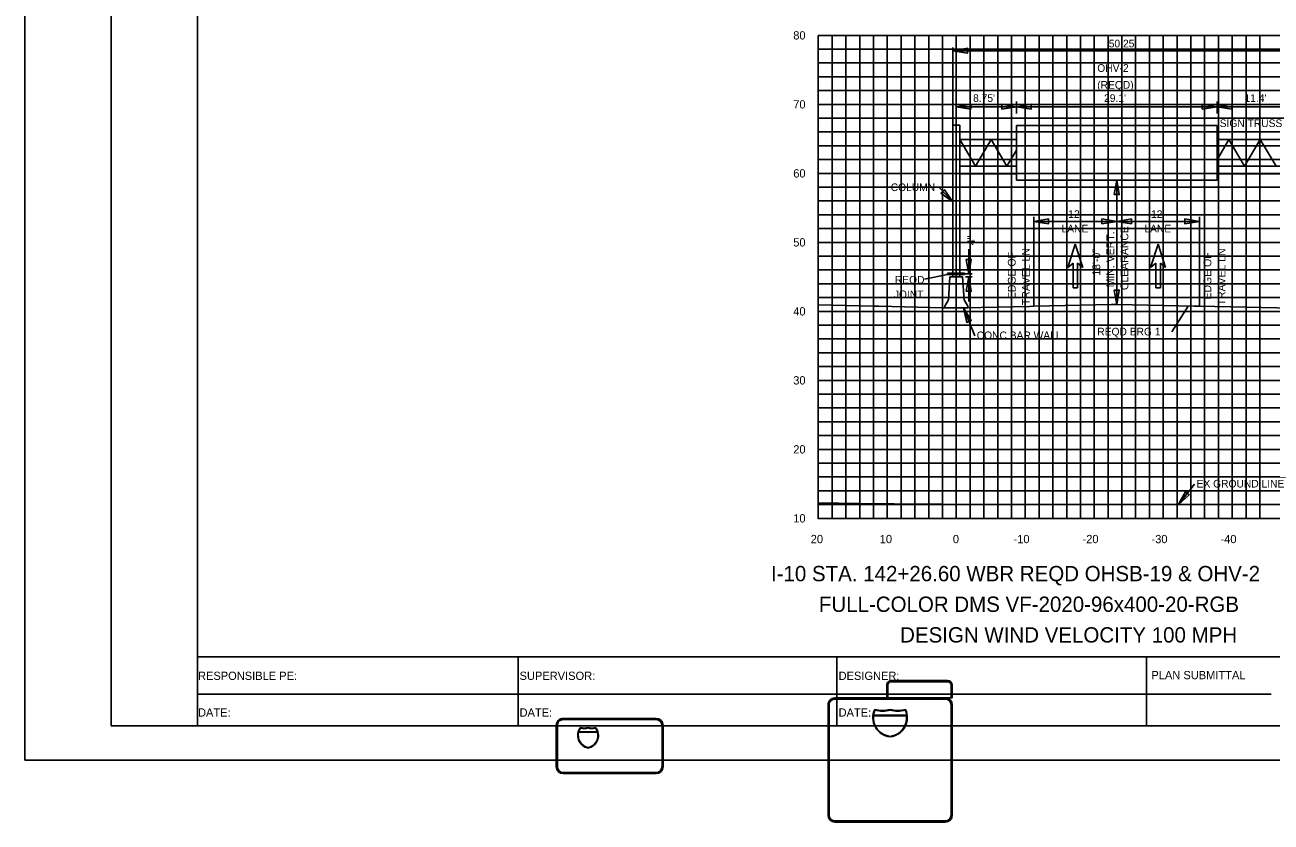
# Model space of a CAD drawing. Extents: x 2193008 to 2198143, y 1236112 to 1237864.
# Drawn here: x 2194857.9 to 2195038.5, y 1237109.1 to 1237224.6 of the extents above; entities that cross this region are included whole.
import ezdxf

# ---------------------------------------------------------------- set-up
doc = ezdxf.new("R2010")
doc.units = 0
for name, color, linetype in [('10', 7, 'Continuous'), ('3', 7, 'Continuous'), ('31', 7, 'Continuous'), ('60', 7, 'Continuous'), ('ANNO-TXT', 7, 'Continuous'), ('CL-CNST', 7, 'Continuous'), ('GSDIMS', 7, 'Continuous'), ('GSOUTLINE', 7, 'Continuous'), ('Level 28', 7, 'Continuous'), ('Level 55', 7, 'Continuous'), ('Level 62', 7, 'Continuous'), ('M-ROADS', 7, 'Continuous'), ('SHT-BDR', 7, 'Continuous'), ('SHT-BNDRY', 7, 'Continuous')]:
    doc.layers.add(name, color=color, linetype=linetype)

msp = doc.modelspace()

# ---------------------------------------------------------------- linework, layer by layer
msp.add_line((2194992.86, 1237208.58), (2194992.86, 1237223.11))
msp.add_lwpolyline([(2194991.19, 1237183.86), (2194991.72, 1237184.77), (2194991.94, 1237188.1), (2194993.78, 1237188.1), (2194994, 1237184.77), (2194994.53, 1237183.86), (2194994.53, 1237183.6), (2194991.19, 1237183.6)], close=True)
at = {"layer": '3'}
for p, q in [((2194992.36, 1237210.11), (2194992.36, 1237221.37)), ((2194992.36, 1237220.88), (2195042.49, 1237220.88)), ((2194992.36, 1237188.1), (2194992.36, 1237210.11)), ((2194993.36, 1237188.1), (2194993.36, 1237210.11)), ((2195001.57, 1237202.11), (2195001.57, 1237210.03)), ((2195030.65, 1237202.11), (2195030.65, 1237210.03)), ((2195016.11, 1237184.11), (2195016.11, 1237202.11)), ((2194992.36, 1237198.99), (2194990.33, 1237201.09)), ((2195004.11, 1237183.85), (2195004.11, 1237196.82)), ((2195028.11, 1237183.85), (2195028.11, 1237196.82)), ((2194994.66, 1237188.54), (2194994.66, 1237192.1)), ((2194988.27, 1237187.76), (2194991.6, 1237188.45)), ((2194994.18, 1237188.54), (2194995.16, 1237188.54)), ((2194994.18, 1237188.1), (2194995.16, 1237188.1)), ((2194994.66, 1237184.55), (2194994.66, 1237188.1)), ((2194995.55, 1237179.58), (2194993.9, 1237183.6)), ((2195024.1, 1237180.16), (2195026.45, 1237183.88)), ((2195027.38, 1237158.07), (2195025.03, 1237155.09))]:
    msp.add_line(p, q, dxfattribs=at)
msp.add_lwpolyline([(2194994.07, 1237188.45), (2194991.6, 1237188.45), (2194991.6, 1237188.63), (2194994.07, 1237188.63)], close=True, dxfattribs=at)
at = {"layer": '60'}
for p, q in [((2194972.86, 1237153.11), (2194972.86, 1237223.11)), ((2194972.86, 1237153.05), (2194972.86, 1237153.11)), ((2194972.86, 1237153.11), (2195102.86, 1237153.11)), ((2194982.86, 1237153.05), (2194982.86, 1237153.11)), ((2194992.86, 1237153.05), (2194992.86, 1237153.11)), ((2195002.86, 1237153.05), (2195002.86, 1237153.11)), ((2195012.86, 1237153.05), (2195012.86, 1237153.11)), ((2195022.86, 1237153.05), (2195022.86, 1237153.11)), ((2195032.86, 1237153.05), (2195032.86, 1237153.11))]:
    msp.add_line(p, q, dxfattribs=at)
at = {"layer": 'CL-CNST'}
msp.add_lwpolyline([(2194972.86, 1237184.04), (2194980.84, 1237183.86), (2194981.61, 1237183.85), (2194990.97, 1237183.64), (2194991.61, 1237183.63), (2194992.78, 1237183.6), (2194992.86, 1237183.6), (2194992.86, 1237183.6), (2194992.86, 1237183.6), (2194994.03, 1237183.62), (2194994.11, 1237183.63), (2195003.47, 1237183.83), (2195004.11, 1237183.85), (2195015.34, 1237184.09), (2195016.11, 1237184.11), (2195027.34, 1237183.86), (2195028.11, 1237183.85), (2195039.34, 1237183.6), (2195042.49, 1237183.53)], dxfattribs=at)
at = {"layer": 'GSDIMS'}
for p, q in [((2194992.86, 1237212.77), (2195001.57, 1237212.77)), ((2195001.57, 1237211.79), (2195001.57, 1237213.53)), ((2195001.57, 1237212.77), (2195030.65, 1237212.77)), ((2195030.65, 1237211.79), (2195030.65, 1237213.53)), ((2195030.65, 1237212.77), (2195041.99, 1237212.77)), ((2194992.36, 1237210.11), (2194993.36, 1237210.11)), ((2194993.36, 1237209.11), (2195001.57, 1237209.11)), ((2195001.57, 1237210.03), (2195030.65, 1237210.03)), ((2195030.65, 1237209.11), (2195041.49, 1237209.11)), ((2194993.36, 1237208), (2195001.57, 1237208)), ((2194993.36, 1237208), (2194995.64, 1237204.14)), ((2194997.92, 1237208), (2194995.64, 1237204.14)), ((2194997.92, 1237208), (2195000.2, 1237204.14)), ((2195030.65, 1237208), (2195041.49, 1237208)), ((2195032.37, 1237208), (2195030.65, 1237205.09)), ((2195032.37, 1237208), (2195034.65, 1237204.14)), ((2195036.93, 1237208), (2195034.65, 1237204.14)), ((2195036.93, 1237208), (2195039.21, 1237204.14)), ((2195001.57, 1237206.46), (2195000.2, 1237204.14)), ((2194993.36, 1237204.14), (2195001.57, 1237204.14)), ((2195030.65, 1237204.14), (2195041.49, 1237204.14)), ((2194993.36, 1237203.03), (2195001.57, 1237203.03)), ((2195001.57, 1237202.11), (2195030.65, 1237202.11)), ((2195030.65, 1237203.03), (2195041.49, 1237203.03)), ((2195004.11, 1237196.15), (2195016.11, 1237196.15)), ((2195016.11, 1237196.15), (2195028.11, 1237196.15))]:
    msp.add_line(p, q, dxfattribs=at)
for points in [[(2194992.36, 1237220.88), (2194994.49, 1237220.54), (2194994.49, 1237221.23)], [(2194992.86, 1237212.77), (2194994.99, 1237212.43), (2194994.99, 1237213.12)], [(2195001.57, 1237212.77), (2194999.44, 1237212.43), (2194999.44, 1237213.12)], [(2195001.57, 1237212.77), (2195003.7, 1237212.43), (2195003.7, 1237213.12)], [(2195030.65, 1237212.77), (2195028.52, 1237212.43), (2195028.52, 1237213.12)], [(2195030.65, 1237212.77), (2195032.78, 1237212.43), (2195032.78, 1237213.12)], [(2195016.11, 1237202.11), (2195016.47, 1237200.03), (2195015.76, 1237200.03)], [(2194992.36, 1237198.99), (2194990.64, 1237200.26), (2194991.15, 1237200.74)], [(2195004.11, 1237196.15), (2195006.24, 1237195.81), (2195006.24, 1237196.5)], [(2195016.11, 1237196.15), (2195013.98, 1237195.81), (2195013.98, 1237196.5)], [(2195016.11, 1237196.15), (2195018.24, 1237195.81), (2195018.24, 1237196.5)], [(2195028.11, 1237196.15), (2195025.98, 1237195.81), (2195025.98, 1237196.5)], [(2194994.66, 1237188.54), (2194994.31, 1237190.63), (2194995.02, 1237190.63)], [(2194994.66, 1237188.1), (2194995.02, 1237186.02), (2194994.31, 1237186.02)], [(2195016.11, 1237184.11), (2195015.76, 1237186.19), (2195016.47, 1237186.19)], [(2194993.9, 1237183.6), (2194994.38, 1237181.51), (2194995.02, 1237181.79)], [(2195025.03, 1237155.09), (2195026.06, 1237156.96), (2195026.6, 1237156.52)]]:
    msp.add_lwpolyline(points, close=True, dxfattribs=at)
at = {"layer": 'GSOUTLINE'}
for p, q in [((2194983.44, 1237129.6), (2194991.61, 1237129.6)), ((2194991.61, 1237129.6), (2194983.44, 1237129.6)), ((2194991.61, 1237129.43), (2194983.44, 1237129.43)), ((2194982.77, 1237127.09), (2194982.77, 1237128.93)), ((2194982.77, 1237128.93), (2194982.77, 1237127.09)), ((2194982.94, 1237128.93), (2194982.94, 1237127.25)), ((2194992.1, 1237127.25), (2194992.1, 1237128.93)), ((2194992.27, 1237128.93), (2194992.27, 1237127.09)), ((2194992.27, 1237127.09), (2194992.27, 1237128.93)), ((2194974.27, 1237126.08), (2194974.27, 1237110.09)), ((2194974.44, 1237126.08), (2194974.44, 1237110.09)), ((2194991.27, 1237127.08), (2194975.27, 1237127.08)), ((2194991.27, 1237126.91), (2194975.27, 1237126.91)), ((2194982.94, 1237127.09), (2194982.77, 1237127.09)), ((2194982.77, 1237127.09), (2194992.27, 1237127.09)), ((2194982.94, 1237127.25), (2194982.94, 1237127.09)), ((2194992.1, 1237127.09), (2194992.1, 1237127.25)), ((2194992.27, 1237127.09), (2194992.1, 1237127.09)), ((2194992.1, 1237110.09), (2194992.1, 1237126.08)), ((2194992.27, 1237110.09), (2194992.27, 1237126.08)), ((2194949.37, 1237124.11), (2194935.87, 1237124.11)), ((2194949.37, 1237123.95), (2194935.87, 1237123.95)), ((2194934.87, 1237123.11), (2194934.87, 1237117.11)), ((2194935.04, 1237123.11), (2194935.04, 1237117.11)), ((2194950.21, 1237117.11), (2194950.21, 1237123.11)), ((2194950.37, 1237117.11), (2194950.37, 1237123.11)), ((2194935.87, 1237116.27), (2194949.37, 1237116.27)), ((2194935.87, 1237116.11), (2194949.37, 1237116.11)), ((2194975.27, 1237109.26), (2194991.27, 1237109.26)), ((2194975.27, 1237109.09), (2194991.27, 1237109.09))]:
    msp.add_line(p, q, dxfattribs=at)
for points in [[(2194980.86, 1237124.5), (2194985.67, 1237124.5)], [(2194985.66, 1237124.58), (2194980.87, 1237124.58)], [(2194940.87, 1237122.11), (2194938.12, 1237122.11)], [(2194938.14, 1237122.17), (2194940.85, 1237122.17)]]:
    msp.add_lwpolyline(points, dxfattribs=at)
for centre, major_axis, ratio, start_param, end_param in [((2194983.44, 1237128.93), (0.666, 0), 0.999829, 1.570796, 3.141593), ((2194983.44, 1237128.93), (0.666, 0), 0.999829, 1.570796, 3.141593), ((2194983.44, 1237128.93), (0.5, 0), 0.999829, 1.570796, 3.141593), ((2194991.61, 1237128.93), (0.666, 0), 0.999829, 0, 1.570796), ((2194991.61, 1237128.93), (0.666, 0), 0.999829, 0, 1.570796), ((2194991.61, 1237128.93), (0.5, 0), 0.999829, 0, 1.570796), ((2194975.27, 1237126.08), (1, 0), 0.999829, 1.570796, 3.141593), ((2194975.27, 1237126.08), (0.833, 0), 0.999829, 1.570796, 3.141593), ((2194991.27, 1237126.08), (1, 0), 0.999829, 0, 1.570796), ((2194991.27, 1237126.08), (0.833, 0), 0.999829, 0, 1.570796), ((2194935.87, 1237123.11), (1, 0), 0.999829, 1.570796, 3.141593), ((2194935.87, 1237123.11), (0.833, 0), 0.999829, 1.570796, 3.141593), ((2194949.37, 1237123.11), (1, 0), 0.999829, 0, 1.570796), ((2194949.37, 1237123.11), (0.833, 0), 0.999829, 0, 1.570796), ((2194983.6, 1237124.23), (2.83, 0), 0.999829, 2.709569, 4.594469), ((2194983.6, 1237124.23), (2.75, 0), 0.999829, 3.043371, 4.590878), ((2194983.6, 1237124.23), (2.75, 0), 0.999829, 2.735396, 3.01287), ((2194982.15, 1237129.25), (4, 0), 0.999829, 4.428637, 4.996141), ((2194982.15, 1237129.25), (4.08, 0), 0.999829, 4.446475, 4.990194), ((2194984.39, 1237129.25), (4, 0), 0.999829, 4.428637, 4.996141), ((2194982.93, 1237124.23), (2.83, 0), 0.999829, 4.830309, 6.715209), ((2194984.39, 1237129.25), (4.08, 0), 0.999829, 4.434584, 4.978303), ((2194982.93, 1237124.23), (2.75, 0), 0.999829, 4.8339, 6.381407), ((2194982.93, 1237124.23), (2.75, 0), 0.999829, 0.128722, 0.406196), ((2194939.87, 1237121.64), (1.87, 0), 0.997059, 2.472588, 4.511032), ((2194939.87, 1237121.64), (1.81, 0), 0.997059, 2.876207, 4.503988), ((2194939.87, 1237121.64), (1.81, 0), 0.997059, 2.495747, 2.84029), ((2194938.95, 1237124.58), (1.87, 0), 0.997059, 4.415842, 5.008936), ((2194938.95, 1237124.58), (1.94, 0), 0.997059, 4.438241, 4.999094), ((2194940.04, 1237124.58), (1.87, 0), 0.997059, 4.415842, 5.008936), ((2194939.12, 1237121.64), (1.87, 0), 0.997059, 4.913746, 6.95219), ((2194940.04, 1237124.58), (1.94, 0), 0.997059, 4.425684, 4.986537), ((2194939.12, 1237121.64), (1.81, 0), 0.997059, 4.92079, 6.548571), ((2194939.12, 1237121.64), (1.81, 0), 0.997059, 0.301302, 0.645846), ((2194935.87, 1237117.11), (1, 0), 0.999829, 3.141593, 4.712389), ((2194935.87, 1237117.11), (0.833, 0), 0.999829, 3.141593, 4.712389), ((2194949.37, 1237117.11), (1, 0), 0.999829, 4.712389, 6.283185), ((2194949.37, 1237117.11), (0.833, 0), 0.999829, 4.712389, 6.283185), ((2194975.27, 1237110.09), (1, 0), 0.999829, 3.141593, 4.712389), ((2194975.27, 1237110.09), (0.833, 0), 0.999829, 3.141593, 4.712389), ((2194991.27, 1237110.09), (1, 0), 0.999829, 4.712389, 6.283185), ((2194991.27, 1237110.09), (0.833, 0), 0.999829, 4.712389, 6.283185)]:
    msp.add_ellipse(centre, major_axis=major_axis, ratio=ratio, start_param=start_param, end_param=end_param, dxfattribs=at)
at = {"layer": 'Level 28'}
for p, q in [((2195010.11, 1237192.84), (2195009.02, 1237189.45)), ((2195011.2, 1237189.45), (2195010.11, 1237192.84)), ((2195022.11, 1237192.84), (2195021.02, 1237189.45)), ((2195023.2, 1237189.45), (2195022.11, 1237192.84)), ((2195009.02, 1237189.45), (2195009.78, 1237190.09)), ((2195009.78, 1237190.09), (2195009.78, 1237186.51)), ((2195010.44, 1237186.51), (2195010.44, 1237190.09)), ((2195010.44, 1237190.09), (2195011.2, 1237189.45)), ((2195021.02, 1237189.45), (2195021.78, 1237190.09)), ((2195021.78, 1237190.09), (2195021.78, 1237186.51)), ((2195022.44, 1237186.51), (2195022.44, 1237190.09)), ((2195022.44, 1237190.09), (2195023.2, 1237189.45)), ((2195009.78, 1237186.51), (2195010.44, 1237186.51)), ((2195021.78, 1237186.51), (2195022.44, 1237186.51))]:
    msp.add_line(p, q, dxfattribs=at)
at = {"layer": 'Level 62'}
for p, q in [((2194972.86, 1237223.11), (2195102.86, 1237223.11)), ((2194974.86, 1237153.11), (2194974.86, 1237223.11)), ((2194976.86, 1237153.11), (2194976.86, 1237223.11)), ((2194978.86, 1237153.11), (2194978.86, 1237223.11)), ((2194980.86, 1237153.11), (2194980.86, 1237223.11)), ((2194982.86, 1237153.11), (2194982.86, 1237223.11)), ((2194984.86, 1237153.11), (2194984.86, 1237223.11)), ((2194986.86, 1237153.11), (2194986.86, 1237223.11)), ((2194988.86, 1237153.11), (2194988.86, 1237223.11)), ((2194990.86, 1237153.11), (2194990.86, 1237223.11)), ((2194992.86, 1237153.11), (2194992.86, 1237223.11)), ((2194994.86, 1237153.11), (2194994.86, 1237223.11)), ((2194996.86, 1237153.11), (2194996.86, 1237223.11)), ((2194998.86, 1237153.11), (2194998.86, 1237223.11)), ((2195000.86, 1237153.11), (2195000.86, 1237223.11)), ((2195002.86, 1237153.11), (2195002.86, 1237223.11)), ((2195004.86, 1237153.11), (2195004.86, 1237223.11)), ((2195006.86, 1237153.11), (2195006.86, 1237223.11)), ((2195008.86, 1237153.11), (2195008.86, 1237223.11)), ((2195010.86, 1237153.11), (2195010.86, 1237223.11)), ((2195012.86, 1237153.11), (2195012.86, 1237223.11)), ((2195014.86, 1237153.11), (2195014.86, 1237223.11)), ((2195016.86, 1237153.11), (2195016.86, 1237223.11)), ((2195018.86, 1237153.11), (2195018.86, 1237223.11)), ((2195020.86, 1237153.11), (2195020.86, 1237223.11)), ((2195022.86, 1237153.11), (2195022.86, 1237223.11)), ((2195024.86, 1237153.11), (2195024.86, 1237223.11)), ((2195026.86, 1237153.11), (2195026.86, 1237223.11)), ((2195028.86, 1237153.11), (2195028.86, 1237223.11)), ((2195030.86, 1237153.11), (2195030.86, 1237223.11)), ((2195032.86, 1237153.11), (2195032.86, 1237223.11)), ((2195034.86, 1237153.11), (2195034.86, 1237223.11)), ((2195036.86, 1237153.11), (2195036.86, 1237223.11)), ((2194972.86, 1237221.11), (2195102.86, 1237221.11)), ((2194972.86, 1237219.11), (2195102.86, 1237219.11)), ((2194972.86, 1237217.11), (2195102.86, 1237217.11)), ((2194972.86, 1237215.11), (2195102.86, 1237215.11)), ((2194972.86, 1237213.11), (2195102.86, 1237213.11)), ((2194972.86, 1237211.11), (2195102.86, 1237211.11)), ((2194972.86, 1237209.11), (2195102.86, 1237209.11)), ((2194972.86, 1237207.11), (2195102.86, 1237207.11)), ((2194972.86, 1237205.11), (2195102.86, 1237205.11)), ((2194972.86, 1237203.11), (2195102.86, 1237203.11)), ((2194972.86, 1237201.11), (2195102.86, 1237201.11)), ((2194972.86, 1237199.11), (2195102.86, 1237199.11)), ((2194972.86, 1237197.11), (2195102.86, 1237197.11)), ((2194972.86, 1237195.11), (2195102.86, 1237195.11)), ((2194972.86, 1237193.11), (2195102.86, 1237193.11)), ((2194972.86, 1237191.11), (2195102.86, 1237191.11)), ((2194972.86, 1237189.11), (2195102.86, 1237189.11)), ((2194972.86, 1237187.11), (2195102.86, 1237187.11)), ((2194972.86, 1237185.11), (2195102.86, 1237185.11)), ((2194972.86, 1237183.11), (2195102.86, 1237183.11)), ((2194972.86, 1237181.11), (2195102.86, 1237181.11)), ((2194972.86, 1237179.11), (2195102.86, 1237179.11)), ((2194972.86, 1237177.11), (2195102.86, 1237177.11)), ((2194972.86, 1237175.11), (2195102.86, 1237175.11)), ((2194972.86, 1237173.11), (2195102.86, 1237173.11)), ((2194972.86, 1237171.11), (2195102.86, 1237171.11)), ((2194972.86, 1237169.11), (2195102.86, 1237169.11)), ((2194972.86, 1237167.11), (2195102.86, 1237167.11)), ((2194972.86, 1237165.11), (2195102.86, 1237165.11)), ((2194972.86, 1237163.11), (2195102.86, 1237163.11)), ((2194972.86, 1237161.11), (2195102.86, 1237161.11)), ((2194972.86, 1237159.11), (2195102.86, 1237159.11)), ((2194972.86, 1237157.11), (2195102.86, 1237157.11)), ((2194972.86, 1237155.11), (2195102.86, 1237155.11)), ((2194972.86, 1237153.11), (2195102.86, 1237153.11))]:
    msp.add_line(p, q, dxfattribs=at)
msp.add_lwpolyline([(2194857.86, 1237118.04), (2195197.86, 1237118.04), (2195197.86, 1237338.04), (2194857.86, 1237338.04)], close=True, dxfattribs=at)
at = {"layer": 'M-ROADS'}
msp.add_lwpolyline([(2194972.86, 1237155.38), (2194981.84, 1237155.23), (2194981.87, 1237155.23), (2194983.32, 1237155.22), (2194983.85, 1237155.22), (2194997.71, 1237155.14), (2194997.77, 1237155.14), (2194998.19, 1237155.14), (2194999.86, 1237155.11), (2195048.06, 1237155.06)], dxfattribs=at)
at = {"layer": 'SHT-BDR'}
msp.add_lwpolyline([(2194882.86, 1237133.05), (2195182.86, 1237133.05), (2195182.86, 1237323.05), (2194882.86, 1237323.05)], close=True, dxfattribs=at)
at = {"layer": 'SHT-BNDRY'}
for p, q in [((2194882.86, 1237123.04), (2194882.86, 1237133.05)), ((2194929.38, 1237133.05), (2194929.38, 1237123.04)), ((2194975.53, 1237123.04), (2194975.53, 1237133.05)), ((2195020.45, 1237123.04), (2195020.45, 1237133.05)), ((2194882.86, 1237127.65), (2195038.49, 1237127.65))]:
    msp.add_line(p, q, dxfattribs=at)
msp.add_lwpolyline([(2194870.36, 1237123.04), (2195192.86, 1237123.04), (2195192.86, 1237333.04), (2194870.36, 1237333.04)], close=True, dxfattribs=at)

# ---------------------------------------------------------------- texts
at = {"layer": '10'}
for s, p in [('20', (2194971.76, 1237149.51)), ('10', (2194981.76, 1237149.51)), ('0', (2194992.36, 1237149.51)), ('-10', (2195001.16, 1237149.51)), ('-20', (2195011.16, 1237149.51)), ('-30', (2195021.16, 1237149.51)), ('-40', (2195031.16, 1237149.51))]:
    msp.add_text(s, height=1.2, dxfattribs=at).set_placement(p)
at = {"layer": '3'}
msp.add_text('REQD BRG 1', height=1.11, dxfattribs=at).set_placement((2195013.3, 1237179.62))
at = {"layer": '31'}
for s, p in [('80', (2194969.23, 1237222.51)), ('70', (2194969.23, 1237212.51)), ('60', (2194969.23, 1237202.51)), ('50', (2194969.23, 1237192.51)), ('40', (2194969.23, 1237182.51)), ('30', (2194969.23, 1237172.51)), ('20', (2194969.23, 1237162.51)), ('10', (2194969.23, 1237152.51))]:
    msp.add_text(s, height=1.2, dxfattribs=at).set_placement(p)
at = {"layer": 'ANNO-TXT'}
for s, p in [('RESPONSIBLE PE:', (2194882.95, 1237129.69)), ('SUPERVISOR:', (2194929.56, 1237129.69)), ('DESIGNER:', (2194975.8, 1237129.69)), ('PLAN SUBMITTAL', (2195021.14, 1237129.79)), ('DATE:', (2194882.95, 1237124.37)), ('DATE:', (2194929.56, 1237124.37)), ('DATE:', (2194975.8, 1237124.37))]:
    msp.add_text(s, height=1.2, rotation=360, dxfattribs=at).set_placement(p)
at = {"layer": 'Level 55'}
for s, height, p in [("50.25'", 1.11, (2195014.96, 1237221.37)), ("8.75'", 1.11, (2194995.3, 1237213.46)), ("29.1'", 1.11, (2195014.28, 1237213.46)), ("11.4'", 1.11, (2195034.64, 1237213.46)), ('SIGN TRUSS', 1.11, (2195031.04, 1237209.82)), ("12'", 1.11, (2195009.09, 1237196.65)), ("12'", 1.11, (2195021.09, 1237196.65)), ('LANE', 1.11, (2195008.12, 1237194.54)), ('LANE', 1.11, (2195020.13, 1237194.54)), ('CONC BAR WALL', 1.1105, (2194995.82, 1237179.08)), ('EX GROUND LINE', 1.1105, (2195027.7, 1237157.58)), ('I-10 STA. 142+26.60 WBR REQD OHSB-19 & OHV-2', 2.2209, (2194966, 1237143.99)), ('FULL-COLOR DMS VF-2020-96x400-20-RGB', 2.2209, (2194972.94, 1237139.55)), ('DESIGN WIND VELOCITY 100 MPH', 2.2209, (2194984.72, 1237135.11))]:
    msp.add_text(s, height=height, dxfattribs=at).set_placement(p)
for s, height, rotation, p in [('OHV-2', 1.11, 360, (2195013.3, 1237217.82)), ('(REQD)', 1.11, 360, (2195013.29, 1237215.38)), ('COLUMN', 1.11, 360, (2194983.36, 1237200.54)), ('MIN. VERT.', 1.135, 90, (2195015.76, 1237186.59)), ('CLEARANCE', 1.135, 90, (2195017.8, 1237186.19)), ('4"', 1.135, 90, (2194995.59, 1237192.7)), ('EDGE OF', 1.135, 90, (2195001.47, 1237184.88)), ('TRAVEL LN', 1.135, 90, (2195003.52, 1237184.02)), ('18\'-0"', 1.135, 90, (2195013.72, 1237188.28)), ('EDGE OF', 1.135, 90, (2195029.83, 1237184.83)), ('TRAVEL LN', 1.135, 90, (2195031.87, 1237183.97)), ('REQD', 1.11, 360, (2194983.96, 1237187.13)), ('JOINT', 1.11, 360, (2194983.81, 1237185.02))]:
    msp.add_text(s, height=height, rotation=rotation, dxfattribs=at).set_placement(p)

doc.saveas('drawing.dxf')
